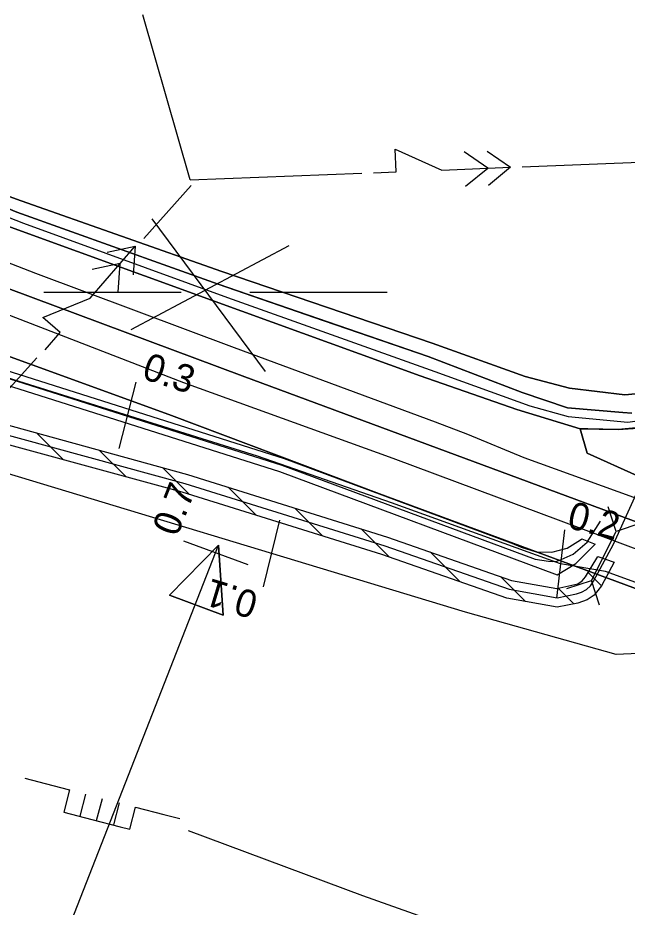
# Model space of a CAD drawing. Extents: x -645676 to -642474, y -1077513 to -1072613.
# Drawn here: x -644873.3 to -644740.3, y -1074904.3 to -1074710.1 of the extents above; entities that cross this region are included whole.
import ezdxf

# ---------------------------------------------------------------- set-up
doc = ezdxf.new("R2010")
doc.units = 0
for name, color, linetype in [('_elezni_n__tra_', 7, 'Continuous'), ('ELEKTRO', 7, 'Continuous'), ('KRAJ_ZELEN_STAV', 7, 'Continuous'), ('KULTURY_STAV', 7, 'Continuous'), ('KULTURY_ZNACKY', 7, 'Continuous'), ('NOVY_STAV', 7, 'Continuous'), ('OSA', 7, 'Continuous'), ('PC_NAVRH', 7, 'Continuous'), ('PC_OBJ_PROP_NAVRH', 7, 'Continuous'), ('PC_STAN_NAVRH', 7, 'Continuous'), ('PLYNOVOD', 7, 'Continuous'), ('Ru_en__prvku_pr_zkumu', 7, 'Continuous'), ('SDELOVACI', 7, 'Continuous'), ('Vodn__plocha___navr_en_', 7, 'Continuous'), ('Vodn__plocha___st_vaj_c_', 7, 'Continuous'), ('Vodn__tok', 7, 'Continuous')]:
    doc.layers.add(name, color=color, linetype=linetype)

# ---------------------------------------------------------------- blocks, each defined once
blk = doc.blocks.new('$944')
blk.add_line((0, 1.5), (0, -1.5))
blk = doc.blocks.new('$920')
for points in [[(0, 0), (-2.8, 1.25), (-2.8, -1.25), (0, 0)], [(-2.8, 1.25), (0, 0), (-2.8, -1.25), (-2.8, 1.25)]]:
    blk.add_lwpolyline(points)
blk = doc.blocks.new('8$0300')
for p, q in [((-7.5, 0), (-1.5, 0)), ((1.5, 0), (7.5, 0))]:
    blk.add_line(p, q)
blk = doc.blocks.new('$939')
for p, q in [((-2, -0.8), (-1.2, 0)), ((2, -0.8), (1.2, 0))]:
    blk.add_line(p, q)
blk.add_lwpolyline([(-2, 0.8), (-1.2, 0), (1.2, 0), (2, 0.8)])
blk = doc.blocks.new('6$3520')
for p, q in [((-0.76, 0), (-0.76, -1)), ((0, -1), (0, 0)), ((0.76, 0), (0.76, -1))]:
    blk.add_line(p, q)
blk.add_lwpolyline([(-3.5, 0), (-2.23, 0), (-1.48, 0), (-1.48, -1), (-0.21, -1), (1.06, -1), (1.5, -1), (1.5, 0), (2.77, 0), (3.5, 0)])
blk = doc.blocks.new('6$6120')
for points in [[(-3, 0), (-2, 0), (-2, 1), (0, 0), (3, 0)], [(1, -0.75), (2, 0), (1, 0.75)], [(2, 0.75), (3, 0), (2, -0.75)]]:
    blk.add_lwpolyline(points)

msp = doc.modelspace()

# ---------------------------------------------------------------- linework, layer by layer
at = {"layer": '_elezni_n__tra_'}
msp.add_lwpolyline([(-645032.05, -1074719.88), (-645007.73, -1074729.17), (-644983.14, -1074736.55), (-644942.37, -1074750.02), (-644914.47, -1074760.84), (-644882.89, -1074772.03), (-644837.1, -1074789.71), (-644791.46, -1074806.27), (-644722.98, -1074831.82), (-644692.05, -1074843.35), (-644645.1, -1074860.33), (-644595.62, -1074879.05), (-644567.2, -1074889.68), (-644538.28, -1074900.75), (-644463.04, -1074928.93), (-644414.14, -1074947.15), (-644324.54, -1074980.78), (-644238.86, -1075012.25), (-644147.17, -1075045.91), (-644073.62, -1075073.69), (-644009.64, -1075097.37)], dxfattribs=at)
at = {"layer": 'ELEKTRO'}
for p, q in [((-644835.65, -1074745.51), (-644846.03, -1074709.48)), ((-644763.2, -1074742.66), (-644515.77, -1074732.93)), ((-644835.65, -1074745.51), (-644798.18, -1074744.03)), ((-644845.82, -1074758.27), (-644835.46, -1074746.72)), ((-644894.22, -1074812.25), (-644869.18, -1074784.33))]:
    msp.add_line(p, q, dxfattribs=at)
at = {"layer": 'KRAJ_ZELEN_STAV'}
msp.add_lwpolyline([(-644748.99, -1074805.18), (-644750.56, -1074799.84), (-644742.26, -1074800.02), (-644732.46, -1074799.34), (-644714.76, -1074806.54), (-644717.25, -1074813.49), (-644738.03, -1074810.09), (-644748.99, -1074805.18)], dxfattribs=at)
at = {"layer": 'KULTURY_STAV'}
for points in [[(-644709.44, -1074581.14), (-644730.58, -1074706.75), (-644732.72, -1074790.92), (-644735.42, -1074791.91), (-644740.74, -1074792.45), (-644752.88, -1074790.98), (-644762.52, -1074788.42), (-644782.83, -1074781.15), (-644828.75, -1074765.49), (-644872.55, -1074750.05), (-644898.87, -1074740.63), (-644904.54, -1074739.03), (-644918.57, -1074735.07), (-644919.51, -1074734.95), (-644939.69, -1074732.49), (-644943.82, -1074722.71), (-644942.47, -1074718.46), (-644938.39, -1074705.57), (-644930.04, -1074685.77), (-644963.2, -1074674.74), (-644974.18, -1074672.5), (-644977.8, -1074671.77), (-645004.38, -1074666.35), (-645021.55, -1074710.42)], [(-644739.24, -1074796.41), (-644741.21, -1074796.25), (-644753.29, -1074795.27), (-644763.22, -1074791.91), (-644783.72, -1074784.05), (-644829.59, -1074768.26), (-644873.51, -1074752.55), (-644899.17, -1074741.74), (-644910.48, -1074738.58), (-644914.98, -1074739.16), (-644918.25, -1074739.58), (-644923.71, -1074743.98), (-644924.76, -1074744.82), (-644925.66, -1074746.09), (-644928.12, -1074749.58), (-644953.82, -1074740.03), (-645006.81, -1074719.35), (-645042.1, -1074704.59)], [(-645042.1, -1074704.59), (-645006.81, -1074719.35), (-644953.82, -1074740.03), (-644928.12, -1074749.58), (-644926.53, -1074750.17), (-644824.29, -1074788.25), (-644721.17, -1074826.46), (-644584.34, -1074877.29), (-644564.38, -1074883.03)], [(-645021.55, -1074710.42), (-645003.54, -1074715.47), (-644949.33, -1074736.78), (-644943.82, -1074722.71), (-644939.69, -1074732.49), (-644919.51, -1074734.95), (-644918.57, -1074735.07), (-644904.54, -1074739.03), (-644898.87, -1074740.63), (-644872.55, -1074750.05), (-644828.75, -1074765.49), (-644782.83, -1074781.15), (-644762.52, -1074788.42), (-644752.88, -1074790.98), (-644740.74, -1074792.45), (-644735.42, -1074791.91)], [(-644564.38, -1074883.03), (-644584.34, -1074877.29), (-644721.17, -1074826.46), (-644824.29, -1074788.25), (-644926.53, -1074750.17), (-644924.29, -1074751), (-644921.99, -1074747.84), (-644916.18, -1074742.45), (-644911.44, -1074741.81), (-644900.01, -1074745.4), (-644874.88, -1074755.82), (-644831.04, -1074771.79), (-644785.45, -1074788.31), (-644764.37, -1074795.64), (-644750.56, -1074799.84), (-644748.99, -1074805.18), (-644738.03, -1074810.09), (-644717.25, -1074813.49), (-644716.55, -1074811.53), (-644714.76, -1074806.54), (-644714.21, -1074806.76), (-644727.89, -1074801.18), (-644630.29, -1074732.74)], [(-644732.46, -1074799.34), (-644742.26, -1074800.02), (-644748.85, -1074799.88), (-644750.56, -1074799.84), (-644764.37, -1074795.64), (-644785.45, -1074788.31), (-644831.04, -1074771.79), (-644874.88, -1074755.82), (-644900.01, -1074745.4), (-644911.44, -1074741.81), (-644916.18, -1074742.45), (-644921.99, -1074747.84), (-644924.29, -1074751), (-644926.53, -1074750.17), (-644928.12, -1074749.58), (-644925.66, -1074746.09), (-644924.76, -1074744.82), (-644923.71, -1074743.98), (-644918.25, -1074739.58), (-644914.98, -1074739.16), (-644910.48, -1074738.58)], [(-644910.48, -1074738.58), (-644899.17, -1074741.74), (-644873.51, -1074752.55), (-644829.59, -1074768.26), (-644783.72, -1074784.05), (-644763.22, -1074791.91), (-644753.29, -1074795.27), (-644741.21, -1074796.25), (-644739.24, -1074796.41)], [(-644571.94, -1074905.75), (-644582.1, -1074898.35), (-644587.88, -1074894.73), (-644599.15, -1074887.69), (-644603.1, -1074886.21), (-644625.37, -1074877.88), (-644648.69, -1074869.15), (-644694.81, -1074851.99), (-644725.16, -1074839.61), (-644735.7, -1074835.71), (-644794.33, -1074814.01), (-644839.75, -1074796.97), (-644886, -1074780.15), (-644917.01, -1074767.86), (-644922.5, -1074768.65), (-644927.17, -1074769.32), (-644934.42, -1074774.52), (-644951.5, -1074803.22), (-644977.86, -1074847.29), (-645008.49, -1074897.01), (-645011.04, -1074900.91)], [(-644917.01, -1074767.86), (-644886, -1074780.15), (-644839.75, -1074796.97), (-644794.33, -1074814.01), (-644735.7, -1074835.71), (-644725.16, -1074839.61), (-644694.81, -1074851.99), (-644648.69, -1074869.15), (-644625.37, -1074877.88), (-644599.15, -1074887.69), (-644587.88, -1074894.73), (-644582.1, -1074898.35), (-644571.94, -1074905.75)], [(-644732.93, -1074799.15), (-644727.89, -1074801.18), (-644714.21, -1074806.76), (-644714.76, -1074806.54), (-644716.55, -1074811.53), (-644717.25, -1074813.49), (-644738.03, -1074810.09), (-644748.99, -1074805.18), (-644750.56, -1074799.84), (-644748.85, -1074799.88), (-644742.26, -1074800.02), (-644732.46, -1074799.34), (-644732.93, -1074799.15)]]:
    msp.add_lwpolyline(points, dxfattribs=at)
at = {"layer": 'NOVY_STAV'}
for points in [[(-645338.95, -1074855.57), (-645302.15, -1074804.17), (-645264.81, -1074753.42), (-645236.22, -1074720.78), (-645204.21, -1074695.1), (-645184.64, -1074686.55), (-645169.47, -1074684.81), (-645164.45, -1074684.55), (-645159.43, -1074684.93), (-645154.51, -1074685.93), (-645143.42, -1074688.92), (-645139.79, -1074690.06), (-645136.27, -1074691.49), (-645132.87, -1074693.2), (-645092.84, -1074715.4), (-645051.12, -1074735.25), (-644974.57, -1074758.92), (-644816.15, -1074809.18), (-644755.54, -1074831.7), (-644751.49, -1074829.28), (-644747.27, -1074825.06)], [(-645050.03, -1074732.45), (-644973.68, -1074756.05), (-644815.17, -1074806.35), (-644765.11, -1074824.94), (-644764.76, -1074825.07), (-644764.42, -1074825.22), (-644764.08, -1074825.37), (-644763.37, -1074825.71), (-644760.1, -1074826.71), (-644756.68, -1074826.77), (-644753.37, -1074825.88), (-644750.45, -1074824.1), (-644750.16, -1074823.86), (-644747.27, -1074825.06)]]:
    msp.add_lwpolyline(points, dxfattribs=at)
at = {"layer": 'OSA'}
msp.add_lwpolyline([(-645035.91, -1074738.38), (-644974.13, -1074757.49), (-644815.66, -1074807.76), (-644760.32, -1074828.3), (-644757.44, -1074828.77), (-644756.51, -1074828.83), (-644755.59, -1074828.71), (-644754.7, -1074828.41), (-644752.08, -1074827.23), (-644749.02, -1074824.57), (-644746.07, -1074820.04)], dxfattribs=at)
at = {"layer": 'PC_NAVRH'}
for points in [[(-644567.19, -1074898.23), (-644579.49, -1074893.18), (-644609.51, -1074881.01), (-644677.32, -1074855.63), (-644745, -1074831.03), (-644754.83, -1074829.35), (-644791.71, -1074816.01), (-644820.96, -1074805.79), (-644875.57, -1074788.7), (-644932.63, -1074770.57), (-645017.52, -1074743.9), (-645048.97, -1074734.32), (-645061.39, -1074728.88), (-645092.58, -1074713.99), (-645134.64, -1074690.69), (-645139.68, -1074688.36), (-645154.82, -1074684.34), (-645162.37, -1074683.15), (-645179.59, -1074665.73)], [(-644726.92, -1074837.45), (-644730.08, -1074844.59), (-644733.42, -1074847.24), (-644737.78, -1074848.88), (-644742.64, -1074849.14), (-644775.59, -1074839.85), (-644889.12, -1074805.55), (-644932.37, -1074792.86), (-644937.59, -1074792.15), (-644944.85, -1074793.38), (-644949.65, -1074796.55), (-644952.92, -1074800.84), (-644967.24, -1074824.68), (-645035.16, -1074931.94), (-645112.98, -1075054.64)], [(-644606.41, -1075221.19), (-644836.11, -1075174.98), (-644844.56, -1075176.95), (-644881.27, -1075159.75), (-644907.13, -1075151.69), (-644922.26, -1075148.52), (-644947.39, -1075148.27), (-644953.49, -1075145.83), (-644953.49, -1075141.93), (-644894.93, -1074992.28), (-644829.47, -1074825.22)]]:
    msp.add_lwpolyline(points, dxfattribs=at)
at = {"layer": 'PLYNOVOD'}
msp.add_lwpolyline([(-644836.1, -1074887.55), (-644798.01, -1074901.76), (-644739.28, -1074922.66), (-644711.22, -1074933.27)], dxfattribs=at)
at = {"layer": 'Ru_en__prvku_pr_zkumu'}
for p, q in [((-644819.22, -1074787.32), (-644843.98, -1074754.01)), ((-644848.56, -1074778.15), (-644814.03, -1074759.82))]:
    msp.add_line(p, q, dxfattribs=at)
at = {"layer": 'SDELOVACI'}
msp.add_lwpolyline([(-645028.66, -1074706.96), (-645005.96, -1074713.92), (-644990.69, -1074716.08), (-644979.69, -1074719.8), (-644949.61, -1074734.04), (-644933, -1074740.83), (-644923.71, -1074743.9), (-644918.72, -1074745.46), (-644903.81, -1074752.12), (-644892.73, -1074756.82), (-644869.42, -1074765.85), (-644826.04, -1074782.12), (-644782.18, -1074798.29), (-644775.1, -1074800.98), (-644762.85, -1074806.13), (-644728.62, -1074818.48), (-644692.8, -1074831.01), (-644666.5, -1074840.69), (-644640.09, -1074850.4), (-644608.82, -1074862.69), (-644584.77, -1074871.19), (-644577.64, -1074873.63), (-644564.43, -1074876.66)], dxfattribs=at)
at = {"layer": 'Vodn__plocha___navr_en_'}
for p, q in [((-644863.42, -1074806.58), (-644869.25, -1074800.75)), ((-644849.67, -1074810.33), (-644855.44, -1074804.56)), ((-644835.83, -1074814.17), (-644841.64, -1074808.36)), ((-644821.29, -1074818.71), (-644827.38, -1074812.62)), ((-644806.76, -1074823.24), (-644812.85, -1074817.15)), ((-644792.13, -1074827.87), (-644798.32, -1074821.68)), ((-644776.73, -1074833.27), (-644783.26, -1074826.74)), ((-644745.88, -1074834.12), (-644748.79, -1074831.21)), ((-644762.43, -1074837.57), (-644767.86, -1074832.14)), ((-644751.92, -1074838.08), (-644755.33, -1074834.67))]:
    msp.add_line(p, q, dxfattribs=at)
msp.add_lwpolyline([(-644937.72, -1074781.87), (-644836.28, -1074809.84), (-644792.57, -1074823.47), (-644765.54, -1074832.95), (-644755.59, -1074834.73), (-644751.05, -1074833.68), (-644750.1, -1074833.06), (-644749.38, -1074832.18), (-644746.65, -1074827.73), (-644743.07, -1074828.93), (-644745.87, -1074834.1), (-644747.45, -1074836.16), (-644748.97, -1074837.15), (-644751.07, -1074837.91), (-644755.53, -1074838.8), (-644766.56, -1074836.83), (-644793.83, -1074827.27), (-644837.4, -1074813.68), (-644916.71, -1074792.03)], dxfattribs=at)
msp.add_lwpolyline([(-644937.72, -1074781.87), (-644836.28, -1074809.84), (-644792.57, -1074823.47), (-644765.54, -1074832.95), (-644755.59, -1074834.73), (-644751.05, -1074833.68), (-644750.1, -1074833.06), (-644749.38, -1074832.18), (-644746.65, -1074827.73), (-644743.07, -1074828.93), (-644745.87, -1074834.1), (-644747.45, -1074836.16), (-644748.97, -1074837.15), (-644751.07, -1074837.91), (-644755.53, -1074838.8), (-644766.56, -1074836.83), (-644793.83, -1074827.27), (-644837.4, -1074813.68), (-644916.71, -1074792.03)], dxfattribs=at)
msp.add_lwpolyline([(-644937.72, -1074781.87), (-644836.28, -1074809.84), (-644792.57, -1074823.47), (-644765.54, -1074832.95), (-644755.59, -1074834.73), (-644751.05, -1074833.68), (-644750.1, -1074833.06), (-644749.38, -1074832.18), (-644746.65, -1074827.73), (-644743.07, -1074828.93), (-644745.87, -1074834.1), (-644747.45, -1074836.16), (-644748.97, -1074837.15), (-644751.07, -1074837.91), (-644755.53, -1074838.8), (-644766.56, -1074836.83), (-644793.83, -1074827.27), (-644837.4, -1074813.68), (-644916.71, -1074792.03)], dxfattribs=at)
at = {"layer": 'Vodn__plocha___st_vaj_c_'}
for points in [[(-644929.78, -1074751.93), (-644924.76, -1074744.82), (-644918.25, -1074739.58), (-644910.48, -1074738.58), (-644899.17, -1074741.74), (-644886.34, -1074747.14), (-644873.51, -1074752.55), (-644829.59, -1074768.26), (-644806.66, -1074776.16), (-644783.72, -1074784.05), (-644763.22, -1074791.91), (-644753.29, -1074795.27), (-644739.24, -1074796.41)], [(-644732.93, -1074799.15), (-644742.26, -1074800.02), (-644750.56, -1074799.84), (-644764.37, -1074795.64), (-644785.45, -1074788.3), (-644831.04, -1074771.79), (-644874.88, -1074755.82), (-644900.01, -1074745.4), (-644911.44, -1074741.81), (-644916.18, -1074742.45), (-644921.99, -1074747.84), (-644926.04, -1074753.4), (-644929.78, -1074751.93)], [(-644873.51, -1074752.55), (-644829.59, -1074768.26), (-644806.66, -1074776.16), (-644783.72, -1074784.05), (-644763.22, -1074791.91), (-644753.29, -1074795.27), (-644739.24, -1074796.41)], [(-644732.93, -1074799.15), (-644742.26, -1074800.02), (-644750.56, -1074799.84), (-644764.37, -1074795.64), (-644785.45, -1074788.3), (-644831.04, -1074771.79), (-644874.88, -1074755.82)]]:
    msp.add_lwpolyline(points, dxfattribs=at)
at = {"layer": 'Vodn__tok'}
for points in [[(-645118.46, -1075054.04), (-645116, -1075050.01), (-645085.27, -1075000.55), (-645046.98, -1074940.37), (-645020.72, -1074899.28), (-645016.84, -1074893.24), (-644984.96, -1074842.87), (-644959.03, -1074802.05), (-644937.04, -1074767.99), (-644934.18, -1074763.89), (-644927.51, -1074752.73), (-644922.7, -1074746.9), (-644916.92, -1074741.6), (-644911.15, -1074740.87), (-644899.76, -1074744.07), (-644872.06, -1074754.98), (-644827.55, -1074771.19), (-644782.23, -1074787.3), (-644761.55, -1074794.86), (-644753.14, -1074797.12), (-644740.1, -1074798.4), (-644731, -1074797.09)], [(-644916.18, -1074790.1), (-644836.84, -1074811.76), (-644793.2, -1074825.37), (-644766.05, -1074834.89), (-644755.56, -1074836.76), (-644751.33, -1074835.89), (-644750.2, -1074835.52), (-644749.17, -1074834.92), (-644748.3, -1074834.11), (-644747.62, -1074833.14), (-644743.22, -1074825.06), (-644735.39, -1074807.69)]]:
    msp.add_lwpolyline(points, dxfattribs=at)

# ---------------------------------------------------------------- block references
at = {"layer": 'ELEKTRO'}
for p, xscale, yscale, rotation in [((-644780.69, -1074743.35), 5.000000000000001, 5, 2.2921949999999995), ((-644857.5, -1074771.3), 5, 5.000000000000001, 48.95583)]:
    msp.add_blockref('6$6120', p, dxfattribs=dict(at, xscale=xscale, yscale=yscale, rotation=rotation))
at = {"layer": 'KULTURY_ZNACKY', "xscale": 5, "yscale": 5}
msp.add_blockref('8$0300', (-644830.14, -1074770.04), dxfattribs=at)
at = {"layer": 'PC_OBJ_PROP_NAVRH', "xscale": 5, "yscale": 5.000000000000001, "rotation": 63.192623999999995}
msp.add_blockref('$939', (-644745.36, -1074827.6), dxfattribs=at)
at = {"layer": 'PC_STAN_NAVRH'}
for name, p, xscale, yscale, rotation in [('$944', (-644849.32, -1074796.91), 5.000000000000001, 4.999999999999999, 165.46090999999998), ('$944', (-644817.88, -1074827.08), 5, 5, 166.038044), ('$920', (-644829.47, -1074825.22), 4.999999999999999, 5, 69.79753399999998), ('$944', (-644754.76, -1074829.36), 5, 4.999999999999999, 173.26088699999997), ('$944', (-644830.12, -1074826.89), 4.999999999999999, 5, 69.79753399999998)]:
    msp.add_blockref(name, p, dxfattribs=dict(at, xscale=xscale, yscale=yscale, rotation=rotation))
at = {"layer": 'PLYNOVOD', "xscale": 5, "yscale": 4.999999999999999, "rotation": -14.539759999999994}
msp.add_blockref('6$3520', (-644854.84, -1074880.55), dxfattribs=at)

# ---------------------------------------------------------------- texts
at = {"layer": 'PC_STAN_NAVRH'}
for s, rotation, p in [('0.3', 341.999, (-644846.46, -1074788.8)), ('0.7', 68.583, (-644838.5, -1074823.61)), ('0.2', 345.608, (-644753.63, -1074821.39)), ('0.1', 163.178, (-644820.47, -1074835.69))]:
    msp.add_text(s, height=6, rotation=rotation, dxfattribs=at).set_placement(p)

doc.saveas('drawing.dxf')
